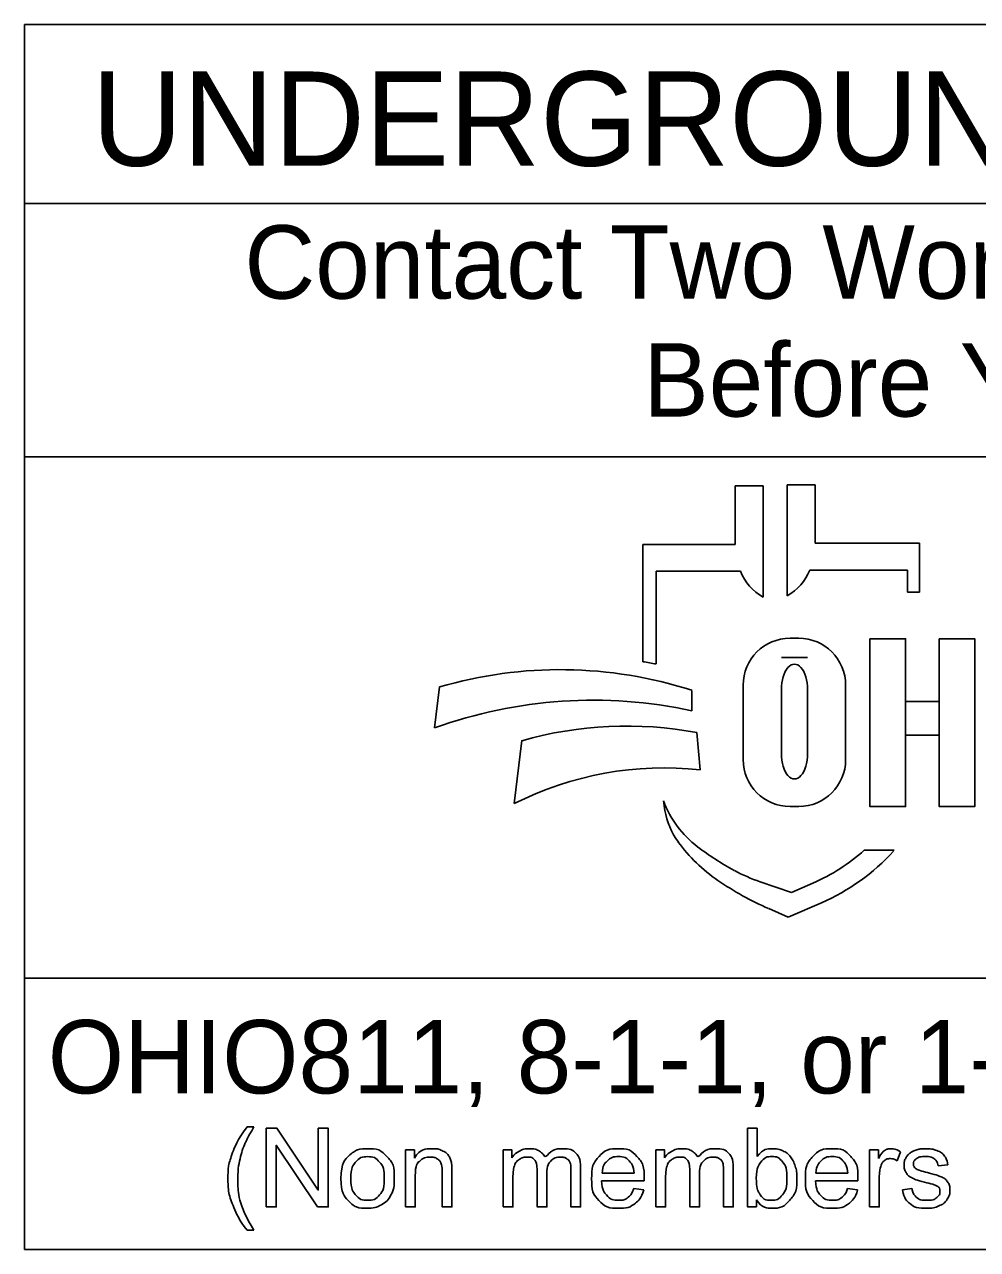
# Model space of a CAD drawing. Extents: x 8.5 to 81.5, y -1.2 to 22.4.
# Drawn here: x 50.33 to 52.149, y 2.493 to 4.831 of the extents above; entities that cross this region are included whole.
import ezdxf

# ---------------------------------------------------------------- set-up
doc = ezdxf.new("R2010")
doc.units = 0
doc.layers.add('SH_Data', color=7, linetype='Continuous')
doc.layers.add('SH_Text', color=7, linetype='Continuous')

msp = doc.modelspace()

# ---------------------------------------------------------------- linework, layer by layer
at = {"layer": 'SH_Data'}
for p, q in [((50.3302, 2.4933), (50.3302, 4.8308)), ((54.5802, 4.8308), (50.3302, 4.8308)), ((50.3302, 4.4893), (54.5802, 4.4893)), ((50.3302, 4.0059), (54.5802, 4.0059)), ((54.5802, 3.0112), (50.3302, 3.0112)), ((54.5802, 2.4933), (50.3302, 2.4933))]:
    msp.add_line(p, q, dxfattribs=at)
at = {"layer": 'SH_Text'}
for p, q in [((51.7856, 3.7406), (51.7856, 3.9527)), ((51.7856, 3.9527), (51.8392, 3.9527)), ((51.8392, 3.9527), (51.8392, 3.8412)), ((51.6863, 3.8389), (51.6863, 3.9503)), ((51.6863, 3.9503), (51.7399, 3.9503)), ((51.7399, 3.9503), (51.7399, 3.7383)), ((51.5103, 3.615), (51.5103, 3.8389)), ((51.5103, 3.8389), (51.6863, 3.8389)), ((51.8392, 3.8412), (52.0385, 3.8412)), ((52.0385, 3.8412), (52.0385, 3.7474)), ((51.5356, 3.7874), (51.5356, 3.6106)), ((51.6967, 3.7874), (51.5356, 3.7874)), ((52.0152, 3.7897), (51.8288, 3.7897)), ((52.0152, 3.7474), (52.0152, 3.7897)), ((52.0385, 3.7474), (52.0152, 3.7474)), ((51.7913, 3.6597), (51.8078, 3.6597)), ((51.8245, 3.6227), (51.7747, 3.6227)), ((51.1129, 3.4887), (51.1223, 3.5668)), ((51.6036, 3.5603), (51.6036, 3.5215)), ((51.7018, 3.4282), (51.7018, 3.5702)), ((51.7747, 3.4396), (51.7747, 3.5619)), ((51.8245, 3.5619), (51.8245, 3.4396)), ((51.8973, 3.5702), (51.8973, 3.4282)), ((51.2648, 3.3441), (51.2795, 3.4643)), ((51.6136, 3.4797), (51.6198, 3.4087)), ((51.5525, 3.3312), (51.5494, 3.3492)), ((51.8078, 3.3387), (51.7913, 3.3387)), ((51.9328, 3.2554), (51.9902, 3.2554)), ((51.7343, 3.195), (51.7937, 3.1745)), ((51.7937, 3.1745), (51.8348, 3.1923)), ((51.7877, 3.1275), (51.7504, 3.1439)), ((51.851, 3.1549), (51.7877, 3.1275))]:
    msp.add_line(p, q, dxfattribs=at)
for points in [[(51.9437, 3.6586), (52.0116, 3.6586), (52.0116, 3.3386), (51.9437, 3.3386)], [(52.0758, 3.6586), (52.1438, 3.6586), (52.1438, 3.3386), (52.0758, 3.3386)], [(52.0116, 3.5387), (52.0758, 3.5387), (52.0758, 3.4747), (52.0116, 3.4747)]]:
    msp.add_lwpolyline(points, close=True, dxfattribs=at)
for points in [[(50.7549, 2.7271), (50.768, 2.7271)], [(50.7916, 2.5745), (50.7916, 2.7246), (50.8119, 2.7246), (50.8909, 2.6067), (50.8909, 2.7246), (50.9099, 2.7246), (50.9099, 2.5745), (50.8896, 2.5745), (50.8106, 2.6924), (50.8106, 2.5745), (50.7916, 2.5745)], [(51.7271, 2.5745), (51.71, 2.5745), (51.71, 2.7246), (51.7284, 2.7246), (51.7284, 2.6711)], [(51.0576, 2.5745), (51.0576, 2.6833), (51.0742, 2.6833), (51.0742, 2.6678)], [(51.244, 2.5745), (51.244, 2.6833), (51.2604, 2.6833), (51.2604, 2.668)], [(51.5353, 2.5745), (51.5353, 2.6833), (51.5518, 2.6833), (51.5518, 2.668)], [(51.9431, 2.5745), (51.9431, 2.6833), (51.9597, 2.6833), (51.9597, 2.6668)], [(52.0022, 2.6798), (51.9957, 2.6628)], [(51.3271, 2.6376), (51.3271, 2.5745), (51.3086, 2.5745), (51.3086, 2.6451)], [(51.3915, 2.6491), (51.3915, 2.5745), (51.3731, 2.5745), (51.3731, 2.643)], [(51.6184, 2.6376), (51.6184, 2.5745), (51.6, 2.5745), (51.6, 2.6451)], [(51.6829, 2.6491), (51.6829, 2.5745), (51.6644, 2.5745), (51.6644, 2.643)], [(52.0921, 2.6552), (52.074, 2.6528)], [(51.076, 2.6339), (51.076, 2.5745), (51.0576, 2.5745)], [(51.1459, 2.6414), (51.1459, 2.5745), (51.1275, 2.5745), (51.1275, 2.6406)], [(51.2624, 2.6309), (51.2624, 2.5745), (51.244, 2.5745)], [(51.5127, 2.6241), (51.4316, 2.6241)], [(51.4326, 2.6393), (51.4934, 2.6393)], [(51.5538, 2.6309), (51.5538, 2.5745), (51.5353, 2.5745)], [(51.9207, 2.6241), (51.8396, 2.6241)], [(51.8406, 2.6393), (51.9014, 2.6393)], [(51.9615, 2.6315), (51.9615, 2.5745), (51.9431, 2.5745)], [(51.4932, 2.6096), (51.5122, 2.6072)], [(51.9011, 2.6096), (51.9202, 2.6072)], [(52.0057, 2.607), (52.0239, 2.6098)], [(51.7271, 2.5881), (51.7271, 2.5745)], [(50.768, 2.5303), (50.7549, 2.5303)]]:
    msp.add_lwpolyline(points, dxfattribs=at)
for centre, radius, start, end in [((51.788, 3.8242), 0.0985, 201.9296, 240.7469), ((51.7375, 3.8265), 0.0985, 299.2531, 338.0704), ((51.7913, 3.5702), 0.0895, 90, 180), ((51.8078, 3.5702), 0.0895, 0, 90), ((51.3524, 2.7807), 0.8191, 72.1402, 106.3144), ((51.3822, 2.806), 0.8191, 79.2074, 81.0007), ((51.4155, 2.6496), 0.8919, 77.8238, 109.8274), ((51.4794, 2.7599), 0.7322, 79.44, 105.8467), ((51.7913, 3.4282), 0.0895, 180, 270), ((51.8078, 3.4282), 0.0895, 270, 0), ((51.5514, 2.7767), 0.6357, 83.8248, 116.8021), ((51.7368, 3.4213), 0.2008, 201.0457, 232.5314), ((51.6938, 3.3553), 0.1433, 189.6817, 216.0884), ((51.8274, 3.4528), 0.3088, 216.0884, 235.7167), ((51.9293, 3.6725), 0.5173, 232.5314, 241.794), ((51.6914, 3.5228), 0.3602, 293.4582, 312.0712), ((51.6914, 3.5228), 0.401, 293.4582, 317.8286), ((51.8442, 3.5137), 0.3371, 241.794, 250.9821), ((51.9939, 3.697), 0.6044, 235.7167, 246.2325)]:
    msp.add_arc(centre, radius, start, end, dxfattribs=at)
for centre, start_param, end_param in [((51.7996, 3.5619), 4.712389, 7.853982), ((51.7996, 3.4396), 1.570796, 4.712389)]:
    msp.add_ellipse(centre, major_axis=(0, 0.0484), ratio=0.514403, start_param=start_param, end_param=end_param, dxfattribs=at)
for points in [[(50.7549, 2.5303), (50.7396, 2.5496), (50.729, 2.5754), (50.7185, 2.6012), (50.7185, 2.6288), (50.7185, 2.6532), (50.7264, 2.6755), (50.7356, 2.7014), (50.7549, 2.7271)], [(50.768, 2.7271), (50.7557, 2.7058), (50.7517, 2.6967), (50.7454, 2.6826), (50.7419, 2.6672), (50.7375, 2.6481), (50.7375, 2.6287), (50.7375, 2.5795), (50.768, 2.5303)], [(50.9341, 2.6289), (50.9341, 2.6591), (50.9509, 2.6736), (50.9649, 2.6857), (50.9851, 2.6857), (51.0075, 2.6857), (51.0217, 2.671), (51.0359, 2.6563), (51.0359, 2.6304), (51.0359, 2.6094), (51.0296, 2.5974), (51.0233, 2.5854), (51.0113, 2.5787), (50.9993, 2.5721), (50.9851, 2.5721), (50.9622, 2.5721), (50.9481, 2.5867), (50.9341, 2.6014), (50.9341, 2.6289)], [(50.9531, 2.6289), (50.9531, 2.608), (50.9622, 2.5976), (50.9713, 2.5872), (50.9851, 2.5872), (50.9987, 2.5872), (51.0078, 2.5976), (51.0169, 2.6081), (51.0169, 2.6295), (51.0169, 2.6497), (51.0078, 2.6601), (50.9986, 2.6705), (50.9851, 2.6705), (50.9713, 2.6705), (50.9622, 2.6601), (50.9531, 2.6498), (50.9531, 2.6289)], [(51.0742, 2.6678), (51.0861, 2.6857), (51.1087, 2.6857), (51.1186, 2.6857), (51.1268, 2.6822), (51.1351, 2.6786), (51.1392, 2.6729), (51.1432, 2.6672), (51.1449, 2.6593), (51.1459, 2.6542), (51.1459, 2.6414)], [(51.1275, 2.6406), (51.1275, 2.6519), (51.1253, 2.6575), (51.1232, 2.663), (51.1177, 2.6664), (51.1122, 2.6697), (51.1049, 2.6697), (51.0931, 2.6697), (51.0845, 2.6622), (51.076, 2.6547), (51.076, 2.6339)], [(51.2604, 2.668), (51.2656, 2.676), (51.2741, 2.6808), (51.2826, 2.6857), (51.2934, 2.6857), (51.3055, 2.6857), (51.3133, 2.6807), (51.321, 2.6757), (51.3242, 2.6666), (51.3371, 2.6857), (51.3578, 2.6857), (51.374, 2.6857), (51.3828, 2.6768), (51.3915, 2.6678), (51.3915, 2.6491)], [(51.3086, 2.6451), (51.3086, 2.6574), (51.3041, 2.6635), (51.2996, 2.6697), (51.2894, 2.6697), (51.2816, 2.6697), (51.275, 2.6656), (51.2683, 2.6615), (51.2654, 2.6536), (51.2624, 2.6457), (51.2624, 2.6309)], [(51.3731, 2.643), (51.3731, 2.654), (51.3713, 2.6589), (51.3695, 2.6638), (51.3648, 2.6667), (51.36, 2.6697), (51.3537, 2.6697), (51.3422, 2.6697), (51.3346, 2.6621), (51.3271, 2.6544), (51.3271, 2.6376)], [(51.5122, 2.6072), (51.5077, 2.5905), (51.4955, 2.5813), (51.4833, 2.5721), (51.4644, 2.5721), (51.4405, 2.5721), (51.4265, 2.5868), (51.4126, 2.6015), (51.4126, 2.628), (51.4126, 2.6554), (51.4267, 2.6706), (51.4408, 2.6857), (51.4634, 2.6857), (51.4852, 2.6857), (51.499, 2.6709), (51.5128, 2.656), (51.5128, 2.6291), (51.5128, 2.6274), (51.5127, 2.6241)], [(51.4934, 2.6393), (51.4921, 2.653), (51.4864, 2.6599), (51.4776, 2.6706), (51.4635, 2.6706), (51.4508, 2.6706), (51.4422, 2.6621), (51.4335, 2.6535), (51.4326, 2.6393)], [(51.5518, 2.668), (51.5569, 2.676), (51.5654, 2.6808), (51.574, 2.6857), (51.5848, 2.6857), (51.5969, 2.6857), (51.6046, 2.6807), (51.6124, 2.6757), (51.6156, 2.6666), (51.6285, 2.6857), (51.6492, 2.6857), (51.6654, 2.6857), (51.6741, 2.6768), (51.6829, 2.6678), (51.6829, 2.6491)], [(51.6, 2.6451), (51.6, 2.6574), (51.5955, 2.6635), (51.591, 2.6697), (51.5807, 2.6697), (51.5729, 2.6697), (51.5663, 2.6656), (51.5597, 2.6615), (51.5567, 2.6536), (51.5538, 2.6457), (51.5538, 2.6309)], [(51.6644, 2.643), (51.6644, 2.654), (51.6626, 2.6589), (51.6608, 2.6638), (51.6561, 2.6667), (51.6514, 2.6697), (51.6451, 2.6697), (51.6336, 2.6697), (51.626, 2.6621), (51.6184, 2.6544), (51.6184, 2.6376)], [(51.7268, 2.6297), (51.7268, 2.6101), (51.7321, 2.6014), (51.7408, 2.5872), (51.7557, 2.5872), (51.7677, 2.5872), (51.7765, 2.5977), (51.7853, 2.6082), (51.7853, 2.629), (51.7853, 2.6503), (51.7769, 2.6605), (51.7684, 2.6706), (51.7565, 2.6706), (51.7444, 2.6706), (51.7356, 2.6601), (51.7268, 2.6496), (51.7268, 2.6297)], [(51.7284, 2.6711), (51.7401, 2.6857), (51.7582, 2.6857), (51.7683, 2.6857), (51.7772, 2.6817), (51.7862, 2.6776), (51.792, 2.6703), (51.7977, 2.663), (51.801, 2.6526), (51.8043, 2.6423), (51.8043, 2.6305), (51.8043, 2.6026), (51.7905, 2.5873), (51.7766, 2.5721), (51.7573, 2.5721), (51.738, 2.5721), (51.7271, 2.5881)], [(51.9202, 2.6072), (51.9157, 2.5905), (51.9035, 2.5813), (51.8913, 2.5721), (51.8724, 2.5721), (51.8485, 2.5721), (51.8345, 2.5868), (51.8206, 2.6015), (51.8206, 2.628), (51.8206, 2.6554), (51.8347, 2.6706), (51.8488, 2.6857), (51.8713, 2.6857), (51.8932, 2.6857), (51.907, 2.6709), (51.9208, 2.656), (51.9208, 2.6291), (51.9208, 2.6274), (51.9207, 2.6241)], [(51.9014, 2.6393), (51.9001, 2.653), (51.8944, 2.6599), (51.8856, 2.6706), (51.8715, 2.6706), (51.8588, 2.6706), (51.8502, 2.6621), (51.8415, 2.6535), (51.8406, 2.6393)], [(51.9597, 2.6668), (51.9661, 2.6784), (51.9714, 2.682), (51.9768, 2.6857), (51.9832, 2.6857), (51.9926, 2.6857), (52.0022, 2.6798)], [(51.9957, 2.6628), (51.989, 2.6667), (51.9823, 2.6667), (51.9762, 2.6667), (51.9715, 2.6631), (51.9667, 2.6594), (51.9646, 2.653), (51.9615, 2.6431), (51.9615, 2.6315)], [(52.074, 2.6528), (52.0728, 2.6612), (52.0669, 2.6659), (52.061, 2.6706), (52.0503, 2.6706), (52.0375, 2.6706), (52.0321, 2.6664), (52.0267, 2.6622), (52.0267, 2.6566), (52.0267, 2.653), (52.0289, 2.6501), (52.0312, 2.6471), (52.036, 2.6452), (52.0388, 2.6441), (52.0523, 2.6404), (52.0719, 2.6352), (52.0797, 2.6319), (52.0874, 2.6286), (52.0918, 2.6222), (52.0962, 2.6159), (52.0962, 2.6065), (52.0962, 2.5973), (52.0909, 2.5891), (52.0855, 2.581), (52.0753, 2.5765), (52.0651, 2.5721), (52.0523, 2.5721), (52.0311, 2.5721), (52.0199, 2.5809), (52.0088, 2.5897), (52.0057, 2.607)], [(52.0239, 2.6098), (52.0255, 2.5989), (52.0325, 2.593), (52.0395, 2.5872), (52.0522, 2.5872), (52.0649, 2.5872), (52.0711, 2.5924), (52.0773, 2.5975), (52.0773, 2.6045), (52.0773, 2.6108), (52.0718, 2.6144), (52.068, 2.6168), (52.0529, 2.6206), (52.0326, 2.6257), (52.0248, 2.6295), (52.0169, 2.6332), (52.0129, 2.6398), (52.0088, 2.6464), (52.0088, 2.6544), (52.0088, 2.6617), (52.0121, 2.6679), (52.0155, 2.674), (52.0212, 2.6781), (52.0255, 2.6813), (52.033, 2.6835), (52.0404, 2.6857), (52.0489, 2.6857), (52.0618, 2.6857), (52.0715, 2.682), (52.0811, 2.6783), (52.0858, 2.672), (52.0904, 2.6657), (52.0921, 2.6552)], [(51.4316, 2.6241), (51.4326, 2.6062), (51.4417, 2.5967), (51.4508, 2.5872), (51.4645, 2.5872), (51.4746, 2.5872), (51.4818, 2.5925), (51.489, 2.5979), (51.4932, 2.6096)], [(51.8396, 2.6241), (51.8406, 2.6062), (51.8497, 2.5967), (51.8588, 2.5872), (51.8724, 2.5872), (51.8826, 2.5872), (51.8898, 2.5925), (51.8969, 2.5979), (51.9011, 2.6096)]]:
    msp.add_open_spline(points, degree=3, dxfattribs=at)

# ---------------------------------------------------------------- texts
for s, height, p in [('UNDERGROUND UTILITIES', 0.18, (50.4584, 4.5612)), ('Contact Two Working Days', 0.14, (50.7499, 4.3077)), ('Before You Dig', 0.14, (51.5111, 4.0827)), ('OHIO811, 8-1-1, or 1-800-362-2764', 0.14, (50.3747, 2.7912))]:
    msp.add_text(s, height=height, dxfattribs=at).set_placement(p)

doc.saveas('drawing.dxf')
